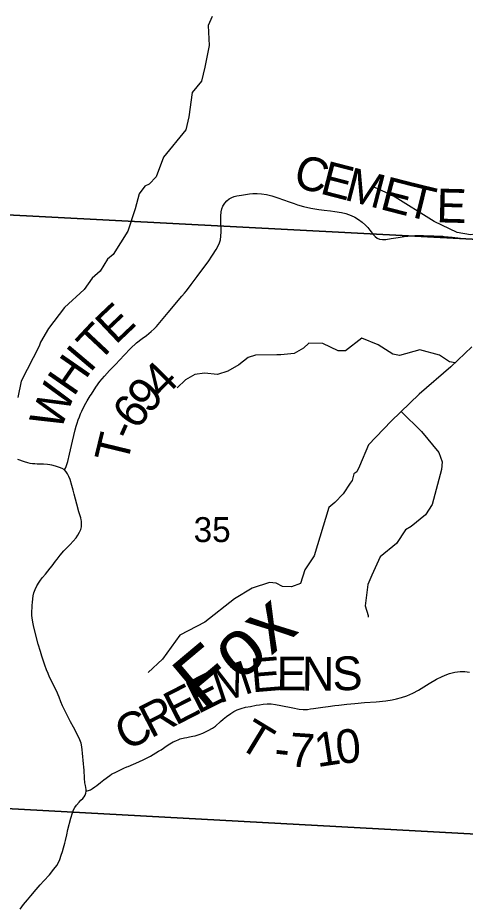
# Model space of a CAD drawing. Extents: x 396.2 to 468.4, y 232.6 to 279.1.
# Drawn here: x 415.736 to 416.488, y 274.409 to 275.903 of the extents above; entities that cross this region are included whole.
import ezdxf

# ---------------------------------------------------------------- set-up
doc = ezdxf.new("R2010")
doc.units = 0
for name, color, linetype in [('GM_X_County_Road', 7, 'Continuous'), ('GM_X_Minor_River', 7, 'Continuous'), ('GM_X_Minor_River_Text', 7, 'Continuous'), ('GM_X_Section', 7, 'Continuous'), ('GM_X_Section_Text', 7, 'Continuous'), ('GM_X_Township_Road', 7, 'Continuous'), ('GM_X_Township_Road_Text', 7, 'Continuous')]:
    doc.layers.add(name, color=color, linetype=linetype)

msp = doc.modelspace()

# ---------------------------------------------------------------- linework, layer by layer
at = {"layer": 'GM_X_County_Road'}
msp.add_lwpolyline([(415.7393, 274.404), (415.7453, 274.4118), (415.752, 274.4199), (415.7576, 274.4266), (415.7665, 274.437), (415.7734, 274.4447), (415.7795, 274.4515), (415.7889, 274.4619), (415.7964, 274.4711), (415.8012, 274.4776), (415.8041, 274.4825), (415.8064, 274.4876), (415.8088, 274.4947), (415.8106, 274.501), (415.8124, 274.5071), (415.8145, 274.515), (415.8156, 274.5192), (415.8179, 274.5292), (415.82, 274.5379), (415.8249, 274.5572), (415.8275, 274.5661), (415.8295, 274.5712), (415.8315, 274.575), (415.8343, 274.579), (415.8387, 274.5842), (415.8416, 274.5871), (415.8448, 274.5903), (415.8473, 274.5932), (415.8489, 274.5959), (415.85, 274.5989), (415.8506, 274.6022), (415.8504, 274.6053), (415.8498, 274.6087), (415.8492, 274.612), (415.8485, 274.6165), (415.8481, 274.6193), (415.848, 274.6218), (415.8478, 274.6246), (415.8471, 274.6379), (415.8467, 274.6428), (415.8462, 274.6485), (415.8444, 274.6663), (415.8438, 274.6722), (415.8433, 274.6769), (415.8421, 274.683), (415.8401, 274.689), (415.8373, 274.6952), (415.8292, 274.71), (415.8241, 274.7191), (415.8207, 274.7256), (415.8178, 274.7312), (415.8142, 274.739), (415.8109, 274.7462), (415.8081, 274.753), (415.8051, 274.7606), (415.8004, 274.7714), (415.7969, 274.7787), (415.7926, 274.7869), (415.789, 274.7941), (415.7864, 274.8005), (415.7839, 274.8067), (415.7812, 274.8142), (415.7786, 274.8213), (415.776, 274.8297), (415.7736, 274.8373), (415.77, 274.8499), (415.763, 274.8763), (415.7619, 274.8812), (415.7607, 274.8865), (415.7596, 274.8939), (415.7594, 274.8982), (415.7593, 274.9018), (415.7594, 274.9062), (415.7596, 274.9095), (415.7598, 274.9154), (415.7601, 274.9199), (415.7606, 274.9258), (415.7616, 274.9312), (415.7628, 274.936), (415.7649, 274.9417), (415.7678, 274.9478), (415.7717, 274.9541), (415.774, 274.9572), (415.7772, 274.9616), (415.7819, 274.9673), (415.7862, 274.9726), (415.7901, 274.9775), (415.7932, 274.9814), (415.7962, 274.9854), (415.7988, 274.9891), (415.8016, 274.9929), (415.807, 274.9997), (415.8131, 275.0067), (415.8196, 275.0134), (415.8235, 275.0173), (415.8287, 275.0228), (415.8335, 275.0285), (415.8367, 275.0331), (415.8394, 275.0381), (415.8414, 275.0428), (415.8425, 275.047), (415.8429, 275.0514), (415.8426, 275.0565), (415.8422, 275.0588), (415.8415, 275.062), (415.84, 275.0672), (415.8385, 275.0722), (415.8347, 275.0854), (415.8302, 275.102), (415.8286, 275.1086), (415.8264, 275.1164), (415.8235, 275.1265), (415.8216, 275.1319), (415.8191, 275.1363), (415.8169, 275.1396), (415.8143, 275.1427), (415.8101, 275.1452), (415.8058, 275.1471), (415.7992, 275.1493), (415.7926, 275.151), (415.7892, 275.1515), (415.7856, 275.1519), (415.7787, 275.1523), (415.7724, 275.1525), (415.7681, 275.1526), (415.7645, 275.1528), (415.7603, 275.1533), (415.7565, 275.1538), (415.7523, 275.1546), (415.7466, 275.1564), (415.7354, 275.1601)], dxfattribs=at)
at = {"layer": 'GM_X_Minor_River'}
for points in [[(416.0624, 275.9058), (416.0557, 275.8902), (416.0572, 275.8568), (416.0499, 275.8202), (416.0446, 275.797), (416.0287, 275.7776), (416.0234, 275.7366), (416.0184, 275.7149), (415.9808, 275.6691)], [(416.6465, 275.6762), (416.6252, 275.6278), (416.5985, 275.5893), (416.5789, 275.5672), (416.5509, 275.5507), (416.5115, 275.5407), (416.4967, 275.5383), (416.4743, 275.5424), (416.4359, 275.5608), (416.3658, 275.6045), (416.3311, 275.6199)], [(415.9808, 275.6691), (415.9681, 275.6361), (415.9564, 275.6236), (415.9491, 275.62), (415.9396, 275.6074), (415.9328, 275.5818), (415.9207, 275.5446), (415.8961, 275.5051), (415.8864, 275.4971), (415.8741, 275.4774), (415.8608, 275.4653), (415.8474, 275.4463), (415.8144, 275.4159), (415.7872, 275.3806), (415.774, 275.3575), (415.7716, 275.3511), (415.7414, 275.2921), (415.7358, 275.2649)], [(416.4711, 275.3227), (416.4613, 275.3245), (416.445, 275.336), (416.4116, 275.3447), (416.3777, 275.3355), (416.3661, 275.3378), (416.3416, 275.353), (416.3143, 275.3645), (416.2865, 275.3434), (416.2744, 275.343), (416.2483, 275.3556), (416.2249, 275.356), (416.2163, 275.3475), (416.2001, 275.3385), (416.1778, 275.3366), (416.1714, 275.3364), (416.1354, 275.3357), (416.1228, 275.3319), (416.1073, 275.3195), (416.0889, 275.3087), (416.0717, 275.3032), (416.0495, 275.3058), (416.0331, 275.3033), (416.0174, 275.2946), (416.0034, 275.281)], [(416.4989, 275.3496), (416.4641, 275.3165), (416.4105, 275.2704), (416.3633, 275.2246), (416.3252, 275.185), (416.3104, 275.1489), (416.3055, 275.1394), (416.3006, 275.1363), (416.298, 275.1249), (416.2946, 275.1203), (416.2829, 275.1028), (416.2686, 275.0878)], [(416.3805, 275.2413), (416.4147, 275.2076), (416.4439, 275.1721), (416.4491, 275.1563), (416.4479, 275.1435), (416.4322, 275.0844), (416.4211, 275.0672), (416.397, 275.0479), (416.3878, 275.0421), (416.3727, 275.019), (416.3452, 274.9964), (416.3307, 274.9657), (416.3245, 274.95), (416.32, 274.914), (416.3248, 274.8979), (416.3248, 274.8951)], [(416.2686, 275.0878), (416.2589, 275.0795), (416.234, 274.9985), (416.2182, 274.9749), (416.2108, 274.9517), (416.1956, 274.9459), (416.1808, 274.9466), (416.1701, 274.9522), (416.1588, 274.9537), (416.1296, 274.9441), (416.1001, 274.9261), (416.0499, 274.8867), (416.0083, 274.8648), (415.9789, 274.8244), (415.9551, 274.8023)]]:
    msp.add_lwpolyline(points, dxfattribs=at)
at = {"layer": 'GM_X_Section'}
for points in [[(415.6539, 276.603), (416.6739, 276.5403), (416.6066, 275.5251), (415.5888, 275.5786), (415.5983, 275.8171)], [(415.5888, 275.5786), (416.6066, 275.5251), (416.5371, 274.5285), (415.5204, 274.5839), (415.5344, 274.7946)], [(415.5204, 274.5839), (416.5371, 274.5285), (416.5087, 274.1071), (416.4804, 273.6869), (416.4687, 273.5133), (415.4502, 273.5695), (415.4623, 273.748)]]:
    msp.add_lwpolyline(points, close=True, dxfattribs=at)
at = {"layer": 'GM_X_Township_Road'}
for points in [[(415.8143, 275.1427), (415.8158, 275.1457), (415.8171, 275.1487), (415.8196, 275.1569), (415.8226, 275.1693), (415.8278, 275.1912), (415.8323, 275.21), (415.8337, 275.2165), (415.8353, 275.2216), (415.8369, 275.2269), (415.8391, 275.2324), (415.8409, 275.237), (415.8433, 275.2417), (415.8452, 275.2457), (415.8502, 275.255), (415.8524, 275.2588), (415.8574, 275.2674), (415.8593, 275.2705), (415.8668, 275.282), (415.8737, 275.2915), (415.8813, 275.3006), (415.8897, 275.3098), (415.8997, 275.32), (415.9147, 275.3356), (415.9252, 275.3468), (415.9352, 275.3564), (415.9445, 275.3637), (415.9521, 275.3691), (415.9598, 275.3756), (415.9647, 275.38), (415.9687, 275.3842), (415.9886, 275.4076), (416.0056, 275.4283), (416.008, 275.4312), (416.0113, 275.4349), (416.0157, 275.4401), (416.0185, 275.4434), (416.0228, 275.4487), (416.0274, 275.4545), (416.0374, 275.4679), (416.0487, 275.4834), (416.0555, 275.4931), (416.0629, 275.5038), (416.0692, 275.5138), (416.0725, 275.5197), (416.0748, 275.5247), (416.0764, 275.53), (416.0773, 275.536), (416.0777, 275.5434), (416.0771, 275.5621), (416.077, 275.5697), (416.0776, 275.5768), (416.0785, 275.5818), (416.0804, 275.5864), (416.0838, 275.5914), (416.0872, 275.5953), (416.091, 275.5986), (416.0954, 275.6012), (416.0996, 275.6028), (416.1042, 275.6041), (416.1116, 275.6052), (416.1252, 275.6071), (416.1308, 275.6076), (416.1383, 275.6079), (416.1457, 275.6074), (416.1537, 275.606), (416.1627, 275.6036), (416.1728, 275.6003), (416.1921, 275.5936), (416.2002, 275.5907), (416.2061, 275.5888), (416.2162, 275.5859), (416.2282, 275.5831), (416.2417, 275.5808), (416.2509, 275.5797), (416.2614, 275.5786), (416.2688, 275.5777), (416.2799, 275.5758), (416.2871, 275.5739), (416.296, 275.5708), (416.3022, 275.5678), (416.3087, 275.5641), (416.3148, 275.5597), (416.3203, 275.5547), (416.3242, 275.5506), (416.3277, 275.5462), (416.3336, 275.5383), (416.3365, 275.5352), (416.3399, 275.5328), (416.3438, 275.5312), (416.3491, 275.5304), (416.3546, 275.5305), (416.3637, 275.5319), (416.3751, 275.534), (416.3818, 275.535), (416.3855, 275.5355), (416.3916, 275.5362), (416.4034, 275.5371), (416.4108, 275.5372), (416.4176, 275.5371), (416.4256, 275.5368), (416.4355, 275.5364), (416.438, 275.5363), (416.4503, 275.5358), (416.4527, 275.5356), (416.4663, 275.5344), (416.4803, 275.5324), (416.4863, 275.532), (416.4926, 275.5316)], [(415.8506, 274.6022), (415.8559, 274.6041), (415.8581, 274.6049), (415.8613, 274.6067), (415.8654, 274.6095), (415.8683, 274.6118), (415.8746, 274.6168), (415.8774, 274.6192), (415.8804, 274.6215), (415.8842, 274.6245), (415.8862, 274.626), (415.8902, 274.6288), (415.8933, 274.6308), (415.9015, 274.6352), (415.9139, 274.6411), (415.919, 274.6432), (415.9213, 274.6441), (415.939, 274.6516), (415.9475, 274.6555), (415.959, 274.6616), (415.9723, 274.6696), (415.9765, 274.6722), (415.9869, 274.679), (415.9914, 274.6821), (415.9968, 274.6852), (416.0011, 274.6874), (416.0062, 274.6895), (416.0086, 274.6903), (416.0157, 274.6921), (416.0198, 274.6929), (416.0242, 274.6938), (416.0297, 274.6949), (416.0339, 274.6958), (416.0405, 274.6976), (416.0468, 274.7001), (416.0557, 274.7043), (416.0632, 274.7086), (416.0678, 274.7119), (416.0767, 274.7196), (416.0812, 274.7234), (416.0866, 274.728), (416.0936, 274.7332), (416.0989, 274.7364), (416.1045, 274.739), (416.1115, 274.7415), (416.1187, 274.7435), (416.1271, 274.7451), (416.1364, 274.7469), (416.142, 274.7478), (416.148, 274.7489), (416.1548, 274.7495), (416.1617, 274.7494), (416.1691, 274.7485), (416.1782, 274.7468), (416.1983, 274.7425), (416.2087, 274.7405), (416.2155, 274.74), (416.2229, 274.7401), (416.2279, 274.7408), (416.2327, 274.7413), (416.2486, 274.7437), (416.2578, 274.745), (416.2689, 274.7466), (416.2756, 274.7474), (416.2892, 274.7489), (416.3021, 274.7501), (416.3188, 274.7516), (416.338, 274.7529), (416.3547, 274.7545), (416.3652, 274.756), (416.3725, 274.7575), (416.3809, 274.7598), (416.3896, 274.7629), (416.3999, 274.7673), (416.4097, 274.7726), (416.4272, 274.7833), (416.4395, 274.7906), (416.449, 274.7954), (416.457, 274.7987), (416.4617, 274.8003), (416.4708, 274.8024), (416.4794, 274.8036), (416.4874, 274.8037), (416.4954, 274.8027)]]:
    msp.add_lwpolyline(points, dxfattribs=at)

# ---------------------------------------------------------------- texts
at = {"layer": 'GM_X_Minor_River_Text'}
msp.add_text('Fox', height=0.0947, rotation=39.9983, dxfattribs=at).set_placement((416.0483, 274.7349))
at = {"layer": 'GM_X_Section_Text'}
msp.add_text('35', height=0.04186, rotation=0, dxfattribs=at).set_placement((416.0313, 275.0215))
at = {"layer": 'GM_X_Township_Road_Text'}
for s, rotation, p in [('C', 345.4961, (416.1967, 275.6199)), ('E', 345.4991, (416.2419, 275.6082)), ('M', 345.4974, (416.283, 275.5976)), ('E', 345.5088, (416.3427, 275.5821)), ('T', 346.228, (416.3846, 275.5713)), ('E', 358.498, (416.439, 275.5594)), ('E', 43.521, (415.9, 275.3524)), ('T', 46.864, (415.8715, 275.322)), ('I', 49.8216, (415.857, 275.3048)), ('H', 55.2707, (415.8294, 275.2648)), ('4', 45.379, (415.9795, 275.2604)), ('W', 68.4344, (415.8068, 275.2066)), ('9', 47.3668, (415.9561, 275.235)), ('6', 53.7457, (415.9365, 275.2081)), ('-', 65.8758, (415.9286, 275.1896)), ('T', 76.3676, (415.9194, 275.1509)), ('M', 18.2748, (416.0744, 274.7498)), ('E', 4.7861, (416.1295, 274.7685)), ('E', 359.7364, (416.1705, 274.772)), ('N', 359.674, (416.213, 274.7718)), ('S', 1.893, (416.2654, 274.7715)), ('E', 26.8315, (416.0385, 274.7315)), ('E', 27.2045, (416.0008, 274.7121)), ('R', 27.2037, (415.9593, 274.6908)), ('C', 27.2039, (415.9178, 274.6695)), ('T', 328.7206, (416.1031, 274.6778)), ('7', 356.1648, (416.1907, 274.6444)), ('1', 8.7737, (416.2392, 274.6427)), ('0', 5.7888, (416.273, 274.6479)), ('-', 353.9493, (416.1651, 274.6471))]:
    msp.add_text(s, height=0.0568, rotation=rotation, dxfattribs=at).set_placement(p)

doc.saveas('drawing.dxf')
